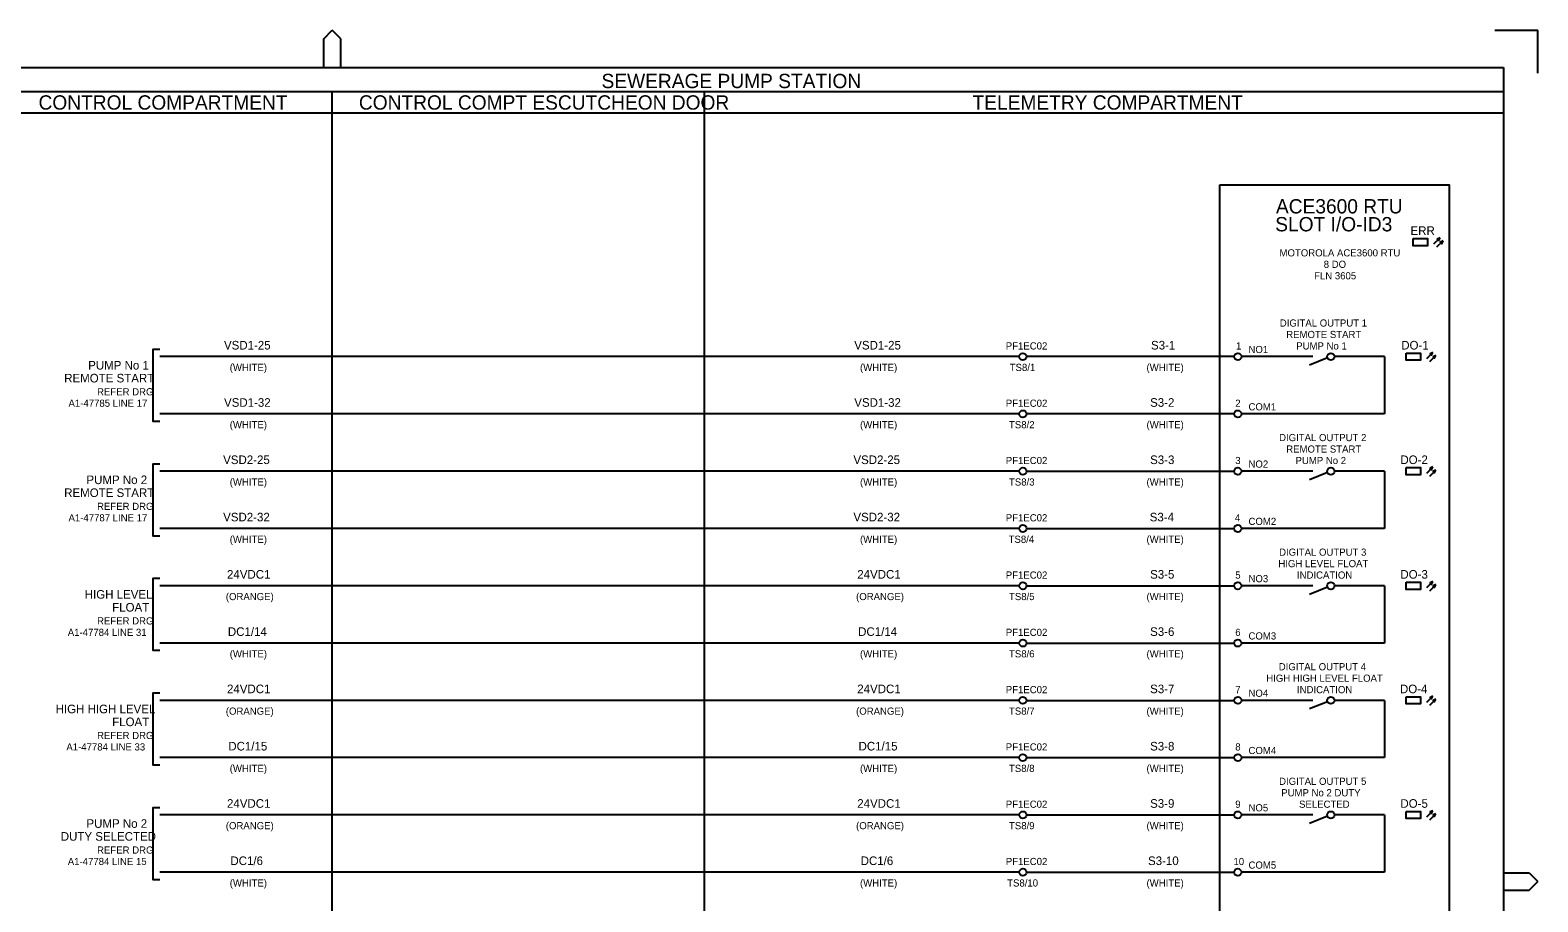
# Model space of a CAD drawing. Extents: x 0 to 841, y 0 to 594.
# Drawn here: x 315 to 841, y 290 to 594 of the extents above; entities that cross this region are included whole.
import ezdxf

# ---------------------------------------------------------------- set-up
doc = ezdxf.new("R2010")
doc.units = 0
for name, color, linetype in [('A1BORDER', 7, 'Continuous'), ('Level 1', 7, 'Continuous'), ('Level 10', 7, 'Continuous')]:
    doc.layers.add(name, color=color, linetype=linetype)

msp = doc.modelspace()

# ---------------------------------------------------------------- linework, layer by layer
at = {"layer": 'A1BORDER'}
for p, q in [((417.19, 591), (420.19, 594)), ((417.19, 581), (417.19, 591)), ((423.19, 591), (420.19, 594)), ((423.19, 581), (423.19, 591)), ((826, 594), (841, 594)), ((841, 579), (841, 594)), ((28, 581), (829, 581)), ((829, 581), (829, 15)), ((829, 299.76), (838, 299.76)), ((838, 299.76), (841, 296.76)), ((838, 293.76), (841, 296.76)), ((829, 293.76), (838, 293.76))]:
    msp.add_line(p, q, dxfattribs=at)
at = {"layer": 'Level 1'}
for p, q in [((829, 572.5), (160, 572.5)), ((420, 572.5), (420, 57)), ((550, 572.5), (550, 57)), ((829, 565), (160, 565)), ((660, 480), (360, 480)), ((735, 480), (662.5, 480)), ((760, 480), (737.5, 480)), ((762.5, 480), (760, 480)), ((787.5, 480), (770, 480)), ((787.5, 480), (787.5, 460)), ((660, 460), (360, 460)), ((735, 460), (662.5, 460)), ((787.5, 460), (737.5, 460)), ((660, 440), (360, 440)), ((662.5, 440), (735, 440)), ((760, 440), (737.5, 440)), ((762.5, 440), (760, 440)), ((787.5, 440), (770, 440)), ((787.5, 440), (787.5, 420)), ((660, 420), (360, 420)), ((662.5, 420), (735, 420)), ((787.5, 420), (737.5, 420)), ((660, 400), (360, 400)), ((662.5, 400), (735, 400)), ((760, 400), (737.5, 400)), ((762.5, 400), (760, 400)), ((787.5, 400), (770, 400)), ((787.5, 400), (787.5, 380)), ((660, 380), (360, 380)), ((662.5, 380), (735, 380)), ((787.5, 380), (737.5, 380)), ((660, 360), (360, 360)), ((662.5, 360), (735, 360)), ((760, 360), (737.5, 360)), ((762.5, 360), (760, 360)), ((787.5, 360), (770, 360)), ((787.5, 360), (787.5, 340)), ((660, 340), (360, 340)), ((662.5, 340), (735, 340)), ((787.5, 340), (737.5, 340)), ((660, 320), (360, 320)), ((662.5, 320), (735, 320)), ((760, 320), (737.5, 320)), ((762.5, 320), (760, 320)), ((787.5, 320), (770, 320)), ((787.5, 320), (787.5, 300)), ((660, 300), (360, 300)), ((662.5, 300), (735, 300)), ((787.5, 300), (737.5, 300))]:
    msp.add_line(p, q, dxfattribs=at)
for points in [[(730, 540), (810, 540), (810, 80), (730, 80)], [(797.5, 521.25), (802.5, 521.25), (802.5, 518.75), (797.5, 518.75)], [(795, 481.25), (800, 481.25), (800, 478.75), (795, 478.75)], [(795, 441.25), (800, 441.25), (800, 438.75), (795, 438.75)], [(795, 401.25), (800, 401.25), (800, 398.75), (795, 398.75)], [(795, 361.25), (800, 361.25), (800, 358.75), (795, 358.75)], [(795, 321.25), (800, 321.25), (800, 318.75), (795, 318.75)]]:
    msp.add_lwpolyline(points, close=True, dxfattribs=at)
for points in [[(360, 482.5), (357.5, 482.5), (357.5, 457.5), (360, 457.5)], [(360, 442.5), (357.5, 442.5), (357.5, 417.5), (360, 417.5)], [(360, 402.5), (357.5, 402.5), (357.5, 377.5), (360, 377.5)], [(360, 362.5), (357.5, 362.5), (357.5, 337.5), (360, 337.5)], [(360, 322.5), (357.5, 322.5), (357.5, 297.5), (360, 297.5)]]:
    msp.add_lwpolyline(points, dxfattribs=at)
for centre in [(661.25, 480), (736.25, 480), (661.25, 460), (736.25, 460), (661.25, 440), (736.25, 440), (661.25, 420), (736.25, 420), (661.25, 400), (736.25, 400), (661.25, 380), (736.25, 380), (661.25, 360), (736.25, 360), (661.25, 340), (736.25, 340), (661.25, 320), (736.25, 320), (661.25, 300), (736.25, 300)]:
    msp.add_circle(centre, 1.25, dxfattribs=at)
at = {"layer": 'Level 10'}
for p, q in [((804.73, 519.36), (806.86, 521.48)), ((805.96, 521.08), (806.67, 521.08)), ((806.29, 521.23), (806.74, 521.23)), ((806.62, 521.38), (806.81, 521.38)), ((805.79, 518.29), (807.91, 520.42)), ((806, 520.92), (806.61, 520.92)), ((806.14, 520.77), (806.53, 520.77)), ((806.3, 520.62), (806.47, 520.62)), ((807.02, 520.01), (807.73, 520.01)), ((807.06, 519.87), (807.66, 519.87)), ((807.21, 519.72), (807.6, 519.72)), ((807.35, 520.16), (807.8, 520.16)), ((807.36, 519.57), (807.53, 519.57)), ((807.68, 520.32), (807.87, 520.32)), ((767.59, 479.54), (761.25, 477)), ((802.23, 479.36), (804.36, 481.48)), ((803.29, 478.3), (805.41, 480.42)), ((803.46, 481.07), (804.17, 481.07)), ((803.5, 480.93), (804.11, 480.93)), ((803.64, 480.78), (804.03, 480.78)), ((803.79, 481.23), (804.24, 481.23)), ((803.8, 480.62), (803.97, 480.62)), ((804.12, 481.38), (804.31, 481.38)), ((804.52, 480.01), (805.23, 480.01)), ((804.56, 479.87), (805.16, 479.87)), ((804.71, 479.72), (805.1, 479.72)), ((804.85, 480.17), (805.3, 480.17)), ((804.86, 479.56), (805.03, 479.56)), ((805.18, 480.31), (805.37, 480.31)), ((767.59, 439.54), (761.25, 437)), ((802.23, 439.36), (804.36, 441.48)), ((803.29, 438.3), (805.41, 440.42)), ((803.46, 441.07), (804.17, 441.07)), ((803.5, 440.93), (804.11, 440.93)), ((803.64, 440.78), (804.03, 440.78)), ((803.79, 441.23), (804.24, 441.23)), ((803.8, 440.62), (803.97, 440.62)), ((804.12, 441.38), (804.31, 441.38)), ((804.52, 440.01), (805.23, 440.01)), ((804.56, 439.87), (805.16, 439.87)), ((804.71, 439.72), (805.1, 439.72)), ((804.85, 440.17), (805.3, 440.17)), ((804.86, 439.56), (805.03, 439.56)), ((805.18, 440.31), (805.37, 440.31)), ((802.23, 399.36), (804.36, 401.48)), ((803.29, 398.3), (805.41, 400.42)), ((803.46, 401.07), (804.17, 401.07)), ((803.5, 400.93), (804.11, 400.93)), ((803.64, 400.78), (804.03, 400.78)), ((803.79, 401.23), (804.24, 401.23)), ((803.8, 400.62), (803.97, 400.62)), ((804.12, 401.38), (804.31, 401.38)), ((804.52, 400.01), (805.23, 400.01)), ((804.85, 400.17), (805.3, 400.17)), ((805.18, 400.31), (805.37, 400.31)), ((767.59, 399.54), (761.25, 397)), ((804.56, 399.87), (805.16, 399.87)), ((804.71, 399.72), (805.1, 399.72)), ((804.86, 399.56), (805.03, 399.56)), ((767.59, 359.54), (761.25, 357)), ((802.23, 359.36), (804.36, 361.48)), ((803.29, 358.3), (805.41, 360.42)), ((803.46, 361.07), (804.17, 361.07)), ((803.5, 360.93), (804.11, 360.93)), ((803.64, 360.78), (804.03, 360.78)), ((803.79, 361.23), (804.24, 361.23)), ((803.8, 360.62), (803.97, 360.62)), ((804.12, 361.38), (804.31, 361.38)), ((804.52, 360.01), (805.23, 360.01)), ((804.56, 359.87), (805.16, 359.87)), ((804.71, 359.72), (805.1, 359.72)), ((804.85, 360.17), (805.3, 360.17)), ((804.86, 359.56), (805.03, 359.56)), ((805.18, 360.31), (805.37, 360.31)), ((802.23, 319.36), (804.36, 321.48)), ((803.46, 321.07), (804.17, 321.07)), ((803.79, 321.23), (804.24, 321.23)), ((804.12, 321.38), (804.31, 321.38)), ((767.59, 319.54), (761.25, 317)), ((803.29, 318.3), (805.41, 320.42)), ((803.5, 320.93), (804.11, 320.93)), ((803.64, 320.78), (804.03, 320.78)), ((803.8, 320.62), (803.97, 320.62)), ((804.52, 320.01), (805.23, 320.01)), ((804.56, 319.87), (805.16, 319.87)), ((804.71, 319.72), (805.1, 319.72)), ((804.85, 320.17), (805.3, 320.17)), ((804.86, 319.56), (805.03, 319.56)), ((805.18, 320.31), (805.37, 320.31))]:
    msp.add_line(p, q, dxfattribs=at)
for points in [[(806.86, 521.48), (805.88, 521.04), (806.41, 520.5)], [(807.91, 520.42), (806.94, 519.98), (807.48, 519.45)], [(804.36, 481.48), (803.38, 481.04), (803.91, 480.5)], [(805.41, 480.42), (804.44, 479.98), (804.98, 479.44)], [(804.36, 441.48), (803.38, 441.04), (803.91, 440.5)], [(805.41, 440.42), (804.44, 439.98), (804.98, 439.44)], [(804.36, 401.48), (803.38, 401.04), (803.91, 400.5)], [(805.41, 400.42), (804.44, 399.98), (804.98, 399.44)], [(804.36, 361.48), (803.38, 361.04), (803.91, 360.5)], [(805.41, 360.42), (804.44, 359.98), (804.98, 359.44)], [(804.36, 321.48), (803.38, 321.04), (803.91, 320.5)], [(805.41, 320.42), (804.44, 319.98), (804.98, 319.44)]]:
    msp.add_lwpolyline(points, close=True, dxfattribs=at)
for centre in [(768.75, 480), (768.75, 440), (768.75, 400), (768.75, 360), (768.75, 320)]:
    msp.add_circle(centre, 1.25, dxfattribs=at)

# ---------------------------------------------------------------- texts
at = {"layer": 'Level 1'}
for s, height, p in [('SEWERAGE PUMP STATION', 5, (514.16, 573.75)), ('CONTROL COMPARTMENT', 5, (317.64, 566.25)), ('CONTROL COMPT ESCUTCHEON DOOR', 5, (429.47, 566.25)), ('TELEMETRY COMPARTMENT', 5, (643.66, 566.25)), ('ACE3600 RTU', 5, (749.58, 530)), ('SLOT I/O-ID3', 5, (749.33, 523.75)), ('ERR', 3, (796.56, 522.5)), ('MOTOROLA ACE3600 RTU', 2.5, (750.83, 515)), ('8 DO', 2.5, (766.26, 511)), ('FLN 3605', 2.5, (762.9, 507)), ('DIGITAL OUTPUT 1', 2.5, (750.93, 490.5)), ('VSD1-25', 3, (382.38, 482.5)), ('VSD1-25', 3, (602.38, 482.5)), ('PF1EC02', 2.5, (655.28, 482.5)), ('S3-1', 3, (705.97, 482.5)), ('1', 2.5, (735.63, 482.5)), ('REMOTE START', 2.5, (753.17, 486.5)), ('PUMP No 1', 2.5, (756.66, 482.5)), ('DO-1', 3, (793.32, 482.5)), ('NO1', 2.5, (740, 481.25)), ('REMOTE START', 3, (326.61, 471)), ('PUMP No 1', 3, (334.98, 475.5)), ('(WHITE)', 2.5, (384.39, 475)), ('(WHITE)', 2.5, (604.39, 475)), ('TS8/1', 2.5, (656.65, 475)), ('(WHITE)', 2.5, (704.4, 475)), ('REFER DRG', 2.5, (338.07, 466.5)), ('A1-47785 LINE 17', 2.5, (328.11, 462.5)), ('VSD1-32', 3, (382.39, 462.5)), ('VSD1-32', 3, (602.39, 462.5)), ('PF1EC02', 2.5, (655.28, 462.5)), ('S3-2', 3, (705.66, 462.5)), ('2', 2.5, (735.38, 462.5)), ('COM1', 2.5, (740, 461.25)), ('(WHITE)', 2.5, (384.39, 455)), ('(WHITE)', 2.5, (604.39, 455)), ('TS8/2', 2.5, (656.4, 455)), ('(WHITE)', 2.5, (704.4, 455)), ('DIGITAL OUTPUT 2', 2.5, (750.68, 450.5)), ('REMOTE START', 2.5, (753.17, 446.5)), ('VSD2-25', 3, (382.09, 442.5)), ('VSD2-25', 3, (602.09, 442.5)), ('PF1EC02', 2.5, (655.28, 442.5)), ('S3-3', 3, (705.66, 442.5)), ('3', 2.5, (735.38, 442.5)), ('NO2', 2.5, (740, 441.25)), ('PUMP No 2', 2.5, (756.41, 442.5)), ('DO-2', 3, (793.02, 442.5)), ('PUMP No 2', 3, (334.38, 435.5)), ('(WHITE)', 2.5, (384.39, 435)), ('(WHITE)', 2.5, (604.39, 435)), ('TS8/3', 2.5, (656.4, 435)), ('(WHITE)', 2.5, (704.4, 435)), ('REMOTE START', 3, (326.61, 431)), ('REFER DRG', 2.5, (338.07, 426.5)), ('A1-47787 LINE 17', 2.5, (328.11, 422.5)), ('VSD2-32', 3, (382.09, 422.5)), ('VSD2-32', 3, (602.09, 422.5)), ('PF1EC02', 2.5, (655.28, 422.5)), ('S3-4', 3, (705.52, 422.5)), ('4', 2.5, (735.25, 422.5)), ('COM2', 2.5, (740, 421.25)), ('(WHITE)', 2.5, (384.39, 415)), ('(WHITE)', 2.5, (604.39, 415)), ('TS8/4', 2.5, (656.27, 415)), ('(WHITE)', 2.5, (704.4, 415)), ('DIGITAL OUTPUT 3', 2.5, (750.68, 410.5)), ('24VDC1', 3, (383.43, 402.5)), ('24VDC1', 3, (603.43, 402.5)), ('S3-5', 3, (705.66, 402.5)), ('HIGH LEVEL FLOAT', 2.5, (750.43, 406.5)), ('DO-3', 3, (793.02, 402.5)), ('PF1EC02', 2.5, (655.28, 402.5)), ('5', 2.5, (735.38, 402.5)), ('NO3', 2.5, (740, 401.25)), ('INDICATION', 2.5, (756.91, 402.5)), ('HIGH LEVEL', 3, (333.78, 395.5)), ('(ORANGE)', 2.5, (383.02, 395)), ('(ORANGE)', 2.5, (603.02, 395)), ('TS8/5', 2.5, (656.4, 395)), ('(WHITE)', 2.5, (704.4, 395)), ('FLOAT', 3, (343.35, 391)), ('A1-47784 LINE 31', 2.5, (327.86, 382.5)), ('REFER DRG', 2.5, (338.07, 386.5)), ('DC1/14', 3, (383.74, 382.5)), ('DC1/14', 3, (603.74, 382.5)), ('PF1EC02', 2.5, (655.28, 382.5)), ('S3-6', 3, (705.66, 382.5)), ('6', 2.5, (735.38, 382.5)), ('COM3', 2.5, (740, 381.25)), ('(WHITE)', 2.5, (384.39, 375)), ('(WHITE)', 2.5, (604.39, 375)), ('TS8/6', 2.5, (656.4, 375)), ('(WHITE)', 2.5, (704.4, 375)), ('HIGH HIGH LEVEL FLOAT', 2.5, (746.2, 366.5)), ('DIGITAL OUTPUT 4', 2.5, (750.56, 370.5)), ('24VDC1', 3, (383.43, 362.5)), ('24VDC1', 3, (603.43, 362.5)), ('PF1EC02', 2.5, (655.28, 362.5)), ('S3-7', 3, (705.66, 362.5)), ('7', 2.5, (735.38, 362.5)), ('NO4', 2.5, (740, 361.25)), ('INDICATION', 2.5, (756.91, 362.5)), ('DO-4', 3, (792.87, 362.5)), ('HIGH HIGH LEVEL', 3, (323.62, 355.5)), ('FLOAT', 3, (343.35, 351)), ('(ORANGE)', 2.5, (383.02, 355)), ('(ORANGE)', 2.5, (603.02, 355)), ('TS8/7', 2.5, (656.4, 355)), ('(WHITE)', 2.5, (704.4, 355)), ('REFER DRG', 2.5, (338.07, 346.5)), ('A1-47784 LINE 33', 2.5, (327.36, 342.5)), ('DC1/15', 3, (383.88, 342.5)), ('DC1/15', 3, (603.88, 342.5)), ('PF1EC02', 2.5, (655.28, 342.5)), ('S3-8', 3, (705.66, 342.5)), ('8', 2.5, (735.38, 342.5)), ('COM4', 2.5, (740, 341.25)), ('(WHITE)', 2.5, (384.39, 335)), ('(WHITE)', 2.5, (604.39, 335)), ('TS8/8', 2.5, (656.4, 335)), ('(WHITE)', 2.5, (704.4, 335)), ('DIGITAL OUTPUT 5', 2.5, (750.68, 330.5)), ('PUMP No 2 DUTY', 2.5, (751.43, 326.5)), ('24VDC1', 3, (383.43, 322.5)), ('24VDC1', 3, (603.43, 322.5)), ('PF1EC02', 2.5, (655.28, 322.5)), ('S3-9', 3, (705.66, 322.5)), ('9', 2.5, (735.38, 322.5)), ('NO5', 2.5, (740, 321.25)), ('SELECTED', 2.5, (757.65, 322.5)), ('DO-5', 3, (793.02, 322.5)), ('PUMP No 2', 3, (334.38, 315.5)), ('(ORANGE)', 2.5, (383.02, 315)), ('(ORANGE)', 2.5, (603.02, 315)), ('TS8/9', 2.5, (656.4, 315)), ('(WHITE)', 2.5, (704.4, 315)), ('DUTY SELECTED', 3, (325.42, 311)), ('REFER DRG', 2.5, (338.07, 306.5)), ('DC1/6', 3, (384.62, 302.5)), ('DC1/6', 3, (604.62, 302.5)), ('S3-10', 3, (704.93, 302.5)), ('A1-47784 LINE 15', 2.5, (327.86, 302.5)), ('PF1EC02', 2.5, (655.28, 302.5)), ('10', 2.5, (734.75, 302.5)), ('COM5', 2.5, (740, 301.25)), ('(WHITE)', 2.5, (384.39, 295)), ('(WHITE)', 2.5, (604.39, 295)), ('TS8/10', 2.5, (655.77, 295)), ('(WHITE)', 2.5, (704.4, 295))]:
    msp.add_text(s, height=height, dxfattribs=at).set_placement(p)

doc.saveas('drawing.dxf')
